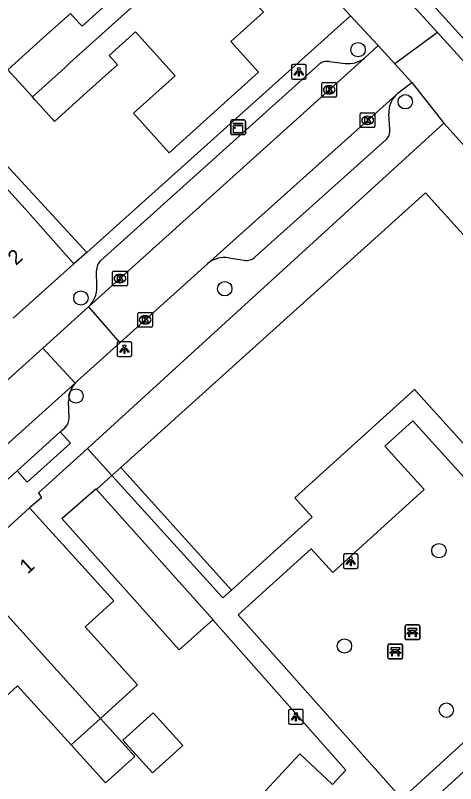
# Model space of a CAD drawing. Extents: x 158352 to 159489, y 383828 to 384597.
# Drawn here: x 159090.2 to 159120.2, y 384109.3 to 384161.6 of the extents above; entities that cross this region are included whole.
import ezdxf

# ---------------------------------------------------------------- set-up
doc = ezdxf.new("R2010")
doc.units = 0
for name, color, linetype in [('IMGEO_Bank', 7, 'Continuous'), ('IMGEO_Boom', 7, 'Continuous'), ('IMGEO_Erf', 7, 'Continuous'), ('IMGEO_Kast', 7, 'Continuous'), ('IMGEO_Kolk', 7, 'Continuous'), ('IMGEO_Lichtpunt', 7, 'Continuous'), ('IMGEO_Pand', 7, 'Continuous'), ('IMGEO_Pand_nummerreeks', 7, 'Continuous'), ('IMGEO_Rijbaan_lokaal_open', 7, 'Continuous'), ('IMGEO_Voetpad_open', 7, 'Continuous')]:
    doc.layers.add(name, color=color, linetype=linetype)

msp = doc.modelspace()

# ---------------------------------------------------------------- linework, layer by layer
at = {"layer": 'IMGEO_Bank'}
for p, q in [((159116.743, 384119.187), (159116.743, 384120.028)), ((159116.743, 384120.028), (159116.743, 384119.187)), ((159116.818, 384120.112), (159117.659, 384120.112)), ((159117.659, 384120.112), (159116.818, 384120.112)), ((159117.052, 384119.618), (159117.052, 384119.724)), ((159117.096, 384119.724), (159117.096, 384119.618)), ((159117.384, 384119.73), (159117.102, 384119.73)), ((159117.39, 384119.618), (159117.39, 384119.724)), ((159117.434, 384119.724), (159117.434, 384119.618)), ((159117.743, 384120.037), (159117.743, 384119.196)), ((159117.743, 384119.196), (159117.743, 384120.037)), ((159117.668, 384119.112), (159116.827, 384119.112)), ((159116.827, 384119.112), (159117.668, 384119.112)), ((159117.44, 384119.51), (159117.047, 384119.51)), ((159117.102, 384119.612), (159117.384, 384119.612)), ((159115.579, 384117.878), (159115.579, 384118.719)), ((159115.579, 384118.719), (159115.579, 384117.878)), ((159115.654, 384118.803), (159116.495, 384118.803)), ((159116.495, 384118.803), (159115.654, 384118.803)), ((159116.579, 384118.728), (159116.579, 384117.887)), ((159116.579, 384117.887), (159116.579, 384118.728)), ((159116.276, 384118.201), (159115.883, 384118.201)), ((159115.888, 384118.309), (159115.888, 384118.415)), ((159115.932, 384118.415), (159115.932, 384118.309)), ((159116.22, 384118.421), (159115.938, 384118.421)), ((159115.938, 384118.303), (159116.22, 384118.303)), ((159116.226, 384118.309), (159116.226, 384118.415)), ((159116.27, 384118.415), (159116.27, 384118.309)), ((159116.504, 384117.803), (159115.663, 384117.803)), ((159115.663, 384117.803), (159116.504, 384117.803))]:
    msp.add_line(p, q, dxfattribs=at)
for points in [[(159117.046, 384119.73), (159116.96, 384119.73), (159116.96, 384119.891), (159117.523, 384119.891), (159117.523, 384119.73), (159117.44, 384119.73)], [(159116.99, 384119.51), (159116.848, 384119.51), (159116.96, 384119.612), (159117.046, 384119.612)], [(159117.04, 384119.503), (159117.04, 384119.296), (159116.997, 384119.296), (159116.997, 384119.503)], [(159117.44, 384119.612), (159117.523, 384119.612), (159117.635, 384119.51), (159117.496, 384119.51)], [(159117.49, 384119.503), (159117.49, 384119.296), (159117.446, 384119.296), (159117.446, 384119.503)], [(159115.882, 384118.421), (159115.796, 384118.421), (159115.796, 384118.582), (159116.359, 384118.582), (159116.359, 384118.421), (159116.276, 384118.421)], [(159115.826, 384118.201), (159115.684, 384118.201), (159115.796, 384118.303), (159115.882, 384118.303)], [(159115.876, 384118.194), (159115.876, 384117.987), (159115.833, 384117.987), (159115.833, 384118.194)], [(159116.276, 384118.303), (159116.359, 384118.303), (159116.471, 384118.201), (159116.332, 384118.201)], [(159116.326, 384118.194), (159116.326, 384117.987), (159116.282, 384117.987), (159116.282, 384118.194)]]:
    msp.add_lwpolyline(points, dxfattribs=at)
for centre, radius, start, end in [((159116.821, 384120.034), 0.0779, 92.4484, 184.2845), ((159116.821, 384120.034), 0.0779, 92.4484, 184.2845), ((159117.045, 384119.723), 0.00671, 2.8957, 87.1043), ((159117.045, 384119.619), 0.00671, 272.8957, 357.1043), ((159117.102, 384119.723), 0.00671, 92.8957, 177.1043), ((159117.102, 384119.619), 0.00671, 182.8957, 267.1043), ((159117.384, 384119.723), 0.00671, 2.8957, 87.1043), ((159117.384, 384119.619), 0.00671, 272.8957, 357.1043), ((159117.441, 384119.723), 0.00671, 92.8957, 177.1043), ((159117.441, 384119.619), 0.00671, 182.8957, 267.1043), ((159117.665, 384120.034), 0.0779, 2.4484, 94.2845), ((159117.665, 384120.034), 0.0779, 2.4484, 94.2845), ((159116.821, 384119.19), 0.0779, 182.4484, 274.2845), ((159116.821, 384119.19), 0.0779, 182.4484, 274.2845), ((159116.99, 384119.503), 0.00671, 2.8957, 87.1043), ((159117.047, 384119.503), 0.00671, 92.8957, 177.1043), ((159117.439, 384119.503), 0.00671, 2.8957, 87.1043), ((159117.496, 384119.503), 0.00671, 92.8957, 177.1043), ((159117.665, 384119.19), 0.0779, 272.4484, 4.2845), ((159117.665, 384119.19), 0.0779, 272.4484, 4.2845), ((159115.657, 384118.725), 0.0779, 92.4484, 184.2845), ((159115.657, 384118.725), 0.0779, 92.4484, 184.2845), ((159116.501, 384118.725), 0.0779, 2.4484, 94.2845), ((159116.501, 384118.725), 0.0779, 2.4484, 94.2845), ((159115.826, 384118.194), 0.00671, 2.8957, 87.1043), ((159115.883, 384118.194), 0.00671, 92.8957, 177.1043), ((159115.881, 384118.414), 0.00671, 2.8957, 87.1043), ((159115.881, 384118.31), 0.00671, 272.8957, 357.1043), ((159115.938, 384118.414), 0.00671, 92.8957, 177.1043), ((159115.938, 384118.31), 0.00671, 182.8957, 267.1043), ((159116.22, 384118.414), 0.00671, 2.8957, 87.1043), ((159116.22, 384118.31), 0.00671, 272.8957, 357.1043), ((159116.277, 384118.414), 0.00671, 92.8957, 177.1043), ((159116.277, 384118.31), 0.00671, 182.8957, 267.1043), ((159116.275, 384118.194), 0.00671, 2.8957, 87.1043), ((159116.332, 384118.194), 0.00671, 92.8957, 177.1043), ((159115.657, 384117.881), 0.0779, 182.4484, 274.2845), ((159115.657, 384117.881), 0.0779, 182.4484, 274.2845), ((159116.501, 384117.881), 0.0779, 272.4484, 4.2845), ((159116.501, 384117.881), 0.0779, 272.4484, 4.2845)]:
    msp.add_arc(centre, radius, start, end, dxfattribs=at)
at = {"layer": 'IMGEO_Boom'}
for centre in [(159113.545, 384159.298), (159116.758, 384155.752), (159104.472, 384143.016), (159094.677, 384142.385), (159094.346, 384135.707), (159119.049, 384125.176), (159112.619, 384118.677), (159119.555, 384114.31)]:
    msp.add_circle(centre, 0.489, dxfattribs=at)
at = {"layer": 'IMGEO_Erf'}
for points in [[(159096.787, 384130.292), (159095.118, 384132.138)], [(159096.787, 384130.292), (159097.388, 384130.835)]]:
    msp.add_lwpolyline(points, dxfattribs=at)
at = {"layer": 'IMGEO_Kast'}
for p, q in [((159104.875, 384153.587), (159104.875, 384154.428)), ((159104.875, 384154.428), (159104.875, 384153.587)), ((159104.95, 384154.512), (159105.791, 384154.512)), ((159105.791, 384154.512), (159104.95, 384154.512)), ((159105.875, 384154.437), (159105.875, 384153.596)), ((159105.875, 384153.596), (159105.875, 384154.437)), ((159105.8, 384153.512), (159104.959, 384153.512)), ((159104.959, 384153.512), (159105.8, 384153.512))]:
    msp.add_line(p, q, dxfattribs=at)
for points in [[(159105.07, 384154.302), (159105.67, 384154.302), (159105.67, 384154.217), (159105.07, 384154.217), (159105.07, 384154.302)], [(159105.07, 384154.127), (159105.67, 384154.127), (159105.67, 384153.638), (159105.07, 384153.638), (159105.07, 384154.127)]]:
    msp.add_lwpolyline(points, dxfattribs=at)
msp.add_circle((159105.154, 384153.976), 0.0377, dxfattribs=at)
for centre, start, end in [((159104.953, 384154.434), 92.4484, 184.2845), ((159104.953, 384154.434), 92.4484, 184.2845), ((159105.797, 384154.434), 2.4484, 94.2845), ((159105.797, 384154.434), 2.4484, 94.2845), ((159104.953, 384153.59), 182.4484, 274.2845), ((159104.953, 384153.59), 182.4484, 274.2845), ((159105.797, 384153.59), 272.4484, 4.2845), ((159105.797, 384153.59), 272.4484, 4.2845)]:
    msp.add_arc(centre, 0.0779, start, end, dxfattribs=at)
at = {"layer": 'IMGEO_Kolk'}
for p, q in [((159111.085, 384156.137), (159111.085, 384156.989)), ((159111.16, 384157.063), (159112.012, 384157.063)), ((159111.573, 384156.843), (159111.598, 384156.843)), ((159112.086, 384156.989), (159112.086, 384156.137)), ((159111.596, 384156.283), (159111.571, 384156.283)), ((159112.012, 384156.063), (159111.16, 384156.063)), ((159113.696, 384154.063), (159113.696, 384154.915)), ((159113.771, 384154.989), (159114.623, 384154.989)), ((159114.184, 384154.769), (159114.209, 384154.769)), ((159114.697, 384154.915), (159114.697, 384154.063)), ((159114.207, 384154.209), (159114.182, 384154.209)), ((159114.623, 384153.989), (159113.771, 384153.989)), ((159096.914, 384144.212), (159097.766, 384144.212)), ((159096.839, 384143.286), (159096.839, 384144.138)), ((159097.327, 384143.992), (159097.352, 384143.992)), ((159097.84, 384144.138), (159097.84, 384143.286)), ((159097.766, 384143.212), (159096.914, 384143.212)), ((159097.35, 384143.432), (159097.325, 384143.432)), ((159098.552, 384140.47), (159098.552, 384141.322)), ((159098.627, 384141.396), (159099.479, 384141.396)), ((159099.04, 384141.176), (159099.065, 384141.176)), ((159099.553, 384141.322), (159099.553, 384140.47)), ((159099.063, 384140.616), (159099.038, 384140.616)), ((159099.479, 384140.396), (159098.627, 384140.396))]:
    msp.add_line(p, q, dxfattribs=at)
for points in [[(159111.085, 384156.137), (159111.085, 384156.989)], [(159111.16, 384157.063), (159112.012, 384157.063)], [(159112.086, 384156.989), (159112.086, 384156.137)], [(159111.406, 384156.763), (159111.529, 384156.763), (159111.529, 384156.612), (159111.659, 384156.763), (159111.823, 384156.763), (159111.677, 384156.612), (159111.83, 384156.363), (159111.678, 384156.363), (159111.593, 384156.527), (159111.529, 384156.46), (159111.529, 384156.363), (159111.406, 384156.363), (159111.406, 384156.763)], [(159112.012, 384156.063), (159111.16, 384156.063)], [(159113.696, 384154.063), (159113.696, 384154.915)], [(159113.771, 384154.989), (159114.623, 384154.989)], [(159114.017, 384154.689), (159114.14, 384154.689), (159114.14, 384154.538), (159114.27, 384154.689), (159114.434, 384154.689), (159114.288, 384154.538), (159114.441, 384154.289), (159114.289, 384154.289), (159114.204, 384154.453), (159114.14, 384154.386), (159114.14, 384154.289), (159114.017, 384154.289), (159114.017, 384154.689)], [(159114.697, 384154.915), (159114.697, 384154.063)], [(159114.623, 384153.989), (159113.771, 384153.989)], [(159096.914, 384144.212), (159097.766, 384144.212)], [(159096.839, 384143.286), (159096.839, 384144.138)], [(159097.16, 384143.912), (159097.283, 384143.912), (159097.283, 384143.761), (159097.413, 384143.912), (159097.577, 384143.912), (159097.431, 384143.761), (159097.584, 384143.512), (159097.432, 384143.512), (159097.347, 384143.676), (159097.283, 384143.609), (159097.283, 384143.512), (159097.16, 384143.512), (159097.16, 384143.912)], [(159097.84, 384144.138), (159097.84, 384143.286)], [(159097.766, 384143.212), (159096.914, 384143.212)], [(159098.552, 384140.47), (159098.552, 384141.322)], [(159098.627, 384141.396), (159099.479, 384141.396)], [(159098.873, 384141.096), (159098.996, 384141.096), (159098.996, 384140.945), (159099.126, 384141.096), (159099.29, 384141.096), (159099.144, 384140.945), (159099.297, 384140.696), (159099.145, 384140.696), (159099.06, 384140.86), (159098.996, 384140.793), (159098.996, 384140.696), (159098.873, 384140.696), (159098.873, 384141.096)], [(159099.553, 384141.322), (159099.553, 384140.47)], [(159099.479, 384140.396), (159098.627, 384140.396)]]:
    msp.add_lwpolyline(points, dxfattribs=at)
for centre, start, end in [((159111.162, 384156.987), 91.552, 178.448), ((159111.162, 384156.987), 91.552, 178.448), ((159112.01, 384156.987), 1.552, 88.448), ((159112.01, 384156.987), 1.552, 88.448), ((159111.162, 384156.139), 181.552, 268.448), ((159111.162, 384156.139), 181.552, 268.448), ((159112.01, 384156.139), 271.552, 358.448), ((159112.01, 384156.139), 271.552, 358.448), ((159113.773, 384154.913), 91.552, 178.448), ((159113.773, 384154.913), 91.552, 178.448), ((159114.621, 384154.913), 1.552, 88.448), ((159114.621, 384154.913), 1.552, 88.448), ((159113.773, 384154.065), 181.552, 268.448), ((159113.773, 384154.065), 181.552, 268.448), ((159114.621, 384154.065), 271.552, 358.448), ((159114.621, 384154.065), 271.552, 358.448), ((159096.916, 384144.136), 91.552, 178.448), ((159096.916, 384144.136), 91.552, 178.448), ((159097.764, 384144.136), 1.552, 88.448), ((159097.764, 384144.136), 1.552, 88.448), ((159096.916, 384143.288), 181.552, 268.448), ((159096.916, 384143.288), 181.552, 268.448), ((159097.764, 384143.288), 271.552, 358.448), ((159097.764, 384143.288), 271.552, 358.448), ((159098.629, 384141.32), 91.552, 178.448), ((159098.629, 384141.32), 91.552, 178.448), ((159099.477, 384141.32), 1.552, 88.448), ((159099.477, 384141.32), 1.552, 88.448), ((159098.629, 384140.472), 181.552, 268.448), ((159098.629, 384140.472), 181.552, 268.448), ((159099.477, 384140.472), 271.552, 358.448), ((159099.477, 384140.472), 271.552, 358.448)]:
    msp.add_arc(centre, 0.0765, start, end, dxfattribs=at)
for centre, major_axis, ratio, start_param, end_param in [((159111.572, 384156.563), (-0.387, 0.002), 0.722429, 4.712389, 7.853982), ((159111.597, 384156.563), (-0.39, 0.002), 0.717154, 1.570796, 4.712389), ((159114.183, 384154.489), (-0.387, 0.002), 0.722429, 4.712389, 7.853982), ((159114.208, 384154.489), (-0.39, 0.002), 0.717154, 1.570796, 4.712389), ((159097.326, 384143.712), (-0.387, 0.002), 0.722429, 4.712389, 7.853982), ((159097.351, 384143.712), (-0.39, 0.002), 0.717154, 1.570796, 4.712389), ((159099.039, 384140.896), (-0.387, 0.002), 0.722429, 4.712389, 7.853982), ((159099.064, 384140.896), (-0.39, 0.002), 0.717154, 1.570796, 4.712389)]:
    msp.add_ellipse(centre, major_axis=major_axis, ratio=ratio, start_param=start_param, end_param=end_param, dxfattribs=at)
at = {"layer": 'IMGEO_Lichtpunt'}
for p, q in [((159109.017, 384158.191), (159109.017, 384157.384)), ((159109.017, 384158.191), (159109.017, 384157.384)), ((159109.919, 384158.286), (159109.111, 384158.286)), ((159109.919, 384158.286), (159109.111, 384158.286)), ((159110.013, 384157.384), (159110.013, 384158.191)), ((159110.013, 384157.384), (159110.013, 384158.191)), ((159109.111, 384157.29), (159109.919, 384157.29)), ((159109.111, 384157.29), (159109.919, 384157.29)), ((159097.143, 384139.301), (159097.143, 384138.494)), ((159097.143, 384139.301), (159097.143, 384138.494)), ((159098.045, 384139.396), (159097.237, 384139.396)), ((159098.045, 384139.396), (159097.237, 384139.396)), ((159098.139, 384138.494), (159098.139, 384139.301)), ((159098.139, 384138.494), (159098.139, 384139.301)), ((159097.237, 384138.4), (159098.045, 384138.4)), ((159097.237, 384138.4), (159098.045, 384138.4)), ((159112.546, 384124.856), (159112.546, 384124.049)), ((159112.546, 384124.856), (159112.546, 384124.049)), ((159113.448, 384124.951), (159112.64, 384124.951)), ((159113.448, 384124.951), (159112.64, 384124.951)), ((159113.542, 384124.049), (159113.542, 384124.856)), ((159113.542, 384124.049), (159113.542, 384124.856)), ((159112.64, 384123.955), (159113.448, 384123.955)), ((159112.64, 384123.955), (159113.448, 384123.955)), ((159108.817, 384114.26), (159108.817, 384113.453)), ((159108.817, 384114.26), (159108.817, 384113.453)), ((159109.719, 384114.355), (159108.911, 384114.355)), ((159109.719, 384114.355), (159108.911, 384114.355)), ((159109.813, 384113.453), (159109.813, 384114.26)), ((159109.813, 384113.453), (159109.813, 384114.26)), ((159108.911, 384113.359), (159109.719, 384113.359)), ((159108.911, 384113.359), (159109.719, 384113.359))]:
    msp.add_line(p, q, dxfattribs=at)
for points in [[(159109.391, 384157.855), (159109.43, 384157.827), (159109.242, 384157.565), (159109.204, 384157.592), (159109.391, 384157.855)], [(159109.603, 384157.827), (159109.641, 384157.854), (159109.828, 384157.592), (159109.789, 384157.564), (159109.603, 384157.827)], [(159109.493, 384157.807), (159109.54, 384157.807), (159109.54, 384157.485), (159109.493, 384157.485), (159109.493, 384157.807)], [(159097.517, 384138.965), (159097.556, 384138.937), (159097.368, 384138.675), (159097.33, 384138.702), (159097.517, 384138.965)], [(159097.619, 384138.917), (159097.666, 384138.917), (159097.666, 384138.595), (159097.619, 384138.595), (159097.619, 384138.917)], [(159097.729, 384138.937), (159097.767, 384138.964), (159097.954, 384138.702), (159097.915, 384138.674), (159097.729, 384138.937)], [(159112.92, 384124.52), (159112.959, 384124.492), (159112.771, 384124.23), (159112.733, 384124.257), (159112.92, 384124.52)], [(159113.022, 384124.472), (159113.069, 384124.472), (159113.069, 384124.15), (159113.022, 384124.15), (159113.022, 384124.472)], [(159113.132, 384124.492), (159113.17, 384124.519), (159113.357, 384124.257), (159113.318, 384124.229), (159113.132, 384124.492)], [(159109.191, 384113.924), (159109.23, 384113.896), (159109.042, 384113.634), (159109.004, 384113.661), (159109.191, 384113.924)], [(159109.293, 384113.876), (159109.34, 384113.876), (159109.34, 384113.554), (159109.293, 384113.554), (159109.293, 384113.876)], [(159109.403, 384113.896), (159109.441, 384113.923), (159109.628, 384113.661), (159109.589, 384113.633), (159109.403, 384113.896)]]:
    msp.add_lwpolyline(points, dxfattribs=at)
for centre in [(159109.516, 384157.989), (159097.642, 384139.099), (159113.045, 384124.654), (159109.316, 384114.058)]:
    msp.add_circle(centre, 0.0994, dxfattribs=at)
for centre, start, end in [((159109.111, 384158.191), 90, 180), ((159109.111, 384158.191), 90, 180), ((159109.919, 384158.191), 0, 90), ((159109.919, 384158.191), 0, 90), ((159109.111, 384157.384), 180, 270), ((159109.111, 384157.384), 180, 270), ((159109.919, 384157.384), 270, 0), ((159109.919, 384157.384), 270, 360), ((159097.237, 384139.301), 90, 180), ((159097.237, 384139.301), 90, 180), ((159098.045, 384139.301), 0, 90), ((159098.045, 384139.301), 0, 90), ((159097.237, 384138.494), 180, 270), ((159097.237, 384138.494), 180, 270), ((159098.045, 384138.494), 270, 0), ((159098.045, 384138.494), 270, 360), ((159112.64, 384124.856), 90, 180), ((159112.64, 384124.856), 90, 180), ((159113.448, 384124.856), 0, 90), ((159113.448, 384124.856), 0, 90), ((159112.64, 384124.049), 180, 270), ((159112.64, 384124.049), 180, 270), ((159113.448, 384124.049), 270, 0), ((159113.448, 384124.049), 270, 360), ((159108.911, 384114.26), 90, 180), ((159108.911, 384114.26), 90, 180), ((159109.719, 384114.26), 0, 90), ((159109.719, 384114.26), 0, 90), ((159108.911, 384113.453), 180, 270), ((159108.911, 384113.453), 180, 270), ((159109.719, 384113.453), 270, 0), ((159109.719, 384113.453), 270, 360)]:
    msp.add_arc(centre, 0.0946, start, end, dxfattribs=at)
at = {"layer": 'IMGEO_Pand'}
for points in [[(159091.375, 384156.086), (159093.577, 384158.072), (159093.933, 384158.393), (159102.932, 384166.51)], [(159102.932, 384166.51), (159107.108, 384161.864), (159104.888, 384159.863), (159106.776, 384157.769), (159100.69, 384152.28), (159098.267, 384154.967), (159101.091, 384157.513), (159098.398, 384160.513), (159096.597, 384158.908), (159097.165, 384158.278), (159095.084, 384156.401), (159092.882, 384154.415), (159091.887, 384155.519), (159091.553, 384155.889), (159091.375, 384156.086)], [(159091.375, 384156.086), (159089.711, 384157.932), (159091.913, 384159.917), (159093.973, 384161.774), (159094.545, 384161.139), (159094.761, 384160.899), (159096.408, 384162.384), (159096.192, 384162.624), (159093.094, 384166.059)], [(159094.209, 384144.717), (159090.884, 384148.451), (159089.322, 384150.194), (159089.225, 384150.106)], [(159097.388, 384130.835), (159118.125, 384149.559), (159139.41, 384125.979), (159136.844, 384123.679), (159138.721, 384121.597), (159139.469, 384122.281), (159139.757, 384121.966), (159139.136, 384121.408), (159144.13, 384115.877), (159130.563, 384103.623), (159122.891, 384112.116)], [(159090.058, 384141.019), (159094.209, 384144.717)], [(159122.891, 384112.116), (159131.826, 384120.187), (159117.389, 384136.145), (159109.234, 384128.768), (159110.42, 384127.456), (159104.931, 384122.493)], [(159104.931, 384122.493), (159097.388, 384130.835)], [(159103.655, 384120.452), (159101.372, 384118.424), (159093.388, 384127.355), (159095.703, 384129.382), (159095.737, 384129.344)], [(159095.737, 384129.344), (159103.673, 384120.468), (159103.655, 384120.452)], [(159086.703, 384124.026), (159091.19, 384128.088)], [(159091.19, 384128.088), (159094.546, 384124.382), (159096.916, 384121.764), (159094.96, 384119.993), (159098.538, 384116.04), (159096.008, 384113.749)], [(159096.008, 384113.749), (159086.703, 384124.026)], [(159094.013, 384111.943), (159090.374, 384115.962), (159087.97, 384113.786)], [(159097.53, 384112.267), (159099.595, 384114.135), (159101.608, 384111.913), (159099.542, 384110.044), (159097.53, 384112.267)], [(159096.008, 384113.749), (159094.013, 384111.943)], [(159096.008, 384113.749), (159098.351, 384111.161), (159096.357, 384109.355), (159094.013, 384111.943)], [(159098.383, 384099.256), (159109.575, 384111.327), (159111.81, 384109.255)]]:
    msp.add_lwpolyline(points, dxfattribs=at)
at = {"layer": 'IMGEO_Rijbaan_lokaal_open'}
for points in [[(159123.06, 384157.482), (159116.392, 384164.857)], [(159113.973, 384158.714), (159114.903, 384159.584)], [(159114.903, 384159.584), (159116.049, 384158.327)], [(159095.196, 384141.775), (159113.973, 384158.714)], [(159116.049, 384158.327), (159117.195, 384157.07)], [(159116.115, 384156.209), (159116.281, 384156.357), (159117.195, 384157.07)], [(159103.296, 384144.719), (159116.115, 384156.209)], [(159097.32, 384139.336), (159103.296, 384144.719)], [(159092.088, 384138.974), (159095.196, 384141.775)], [(159095.196, 384141.775), (159097.32, 384139.336)], [(159097.32, 384139.336), (159094.443, 384136.738), (159094.286, 384136.578)], [(159088.37, 384135.624), (159092.088, 384138.974)], [(159094.286, 384136.578), (159092.088, 384138.974)], [(159094.286, 384136.578), (159071.791, 384116.352)]]:
    msp.add_lwpolyline(points, dxfattribs=at)
at = {"layer": 'IMGEO_Voetpad_open'}
for points in [[(159113.036, 384161.604), (159076.521, 384202.062)], [(159089.225, 384150.106), (159074.513, 384166.093), (159074.61, 384166.182), (159075.381, 384166.892), (159095.074, 384145.493)], [(159118.955, 384160.473), (159115.621, 384164.16), (159116.392, 384164.857)], [(159095.074, 384145.493), (159113.036, 384161.604)], [(159113.036, 384161.604), (159114.903, 384159.584)], [(159118.955, 384160.473), (159116.049, 384158.327)], [(159123.06, 384157.482), (159122.289, 384156.785), (159118.955, 384160.473)], [(159111.572, 384158.497), (159112.658, 384158.364)], [(159096.037, 384144.93), (159110.842, 384158.268)], [(159117.195, 384157.07), (159119.386, 384154.284)], [(159115.718, 384153.872), (159115.648, 384154.941)], [(159119.386, 384154.284), (159095.118, 384132.138)], [(159119.386, 384154.284), (159138.943, 384132.588), (159170.001, 384098.199), (159190.797, 384075.301)], [(159106.542, 384145.181), (159115.428, 384153.161)], [(159095.074, 384145.493), (159094.209, 384144.717)], [(159104.752, 384145.126), (159105.789, 384144.959)], [(159095.771, 384143.163), (159095.739, 384144.234)], [(159093.881, 384134.23), (159093.845, 384135.329)], [(159115.376, 384132.288), (159117.282, 384134.012), (159129.694, 384120.293), (159126.441, 384117.326), (159116.516, 384108.273), (159105.377, 384120.804), (159110.352, 384125.288), (159111.821, 384123.682), (159112.865, 384124.632), (159118.039, 384129.344), (159115.376, 384132.288)], [(159093.276, 384133.264), (159093.971, 384132.491), (159091.032, 384129.849), (159090.337, 384130.622)], [(159090.337, 384130.622), (159093.276, 384133.264)], [(159093.276, 384133.264), (159093.59, 384133.546)], [(159095.118, 384132.138), (159091.797, 384129.107), (159091.987, 384128.777), (159091.19, 384128.088)], [(159074.976, 384116.866), (159080.851, 384122.093), (159090.337, 384130.622)], [(159095.737, 384129.344), (159096.787, 384130.292)], [(159104.931, 384122.493), (159104.33, 384121.95), (159096.787, 384130.292)], [(159111.81, 384109.255), (159112.717, 384110.233), (159103.655, 384120.452)], [(159115.784, 384101.697), (159118.998, 384105.435), (159117.482, 384107.143), (159122.891, 384112.116)]]:
    msp.add_lwpolyline(points, dxfattribs=at)
for centre, radius, start, end in [((159111.457, 384157.585), 0.92, 82.8362, 131.997), ((159112.876, 384160.192), 1.841, 263.2091, 306.5995), ((159117.307, 384155.05), 1.662, 135.8005, 183.7623), ((159114.844, 384153.814), 0.876, 311.8274, 3.7939), ((159096.636, 384144.262), 0.897, 131.8647, 181.7779), ((159104.469, 384143.329), 1.819, 81.0639, 130.171), ((159105.933, 384145.86), 0.912, 260.948, 311.9053), ((159093.924, 384143.115), 1.847, 313.5055, 1.4894), ((159095.653, 384135.393), 1.809, 139.0832, 182.0223), ((159092.998, 384134.202), 0.883, 312.0692, 1.8373)]:
    msp.add_arc(centre, radius, start, end, dxfattribs=at)

# ---------------------------------------------------------------- texts
at = {"layer": 'IMGEO_Pand_nummerreeks'}
for s, rotation, p in [('2', 41.6941, (159090.251, 384144.566)), ('1', 42.1568, (159091.061, 384123.547))]:
    msp.add_text(s, height=1, rotation=rotation, dxfattribs=at).set_placement(p)

doc.saveas('drawing.dxf')
